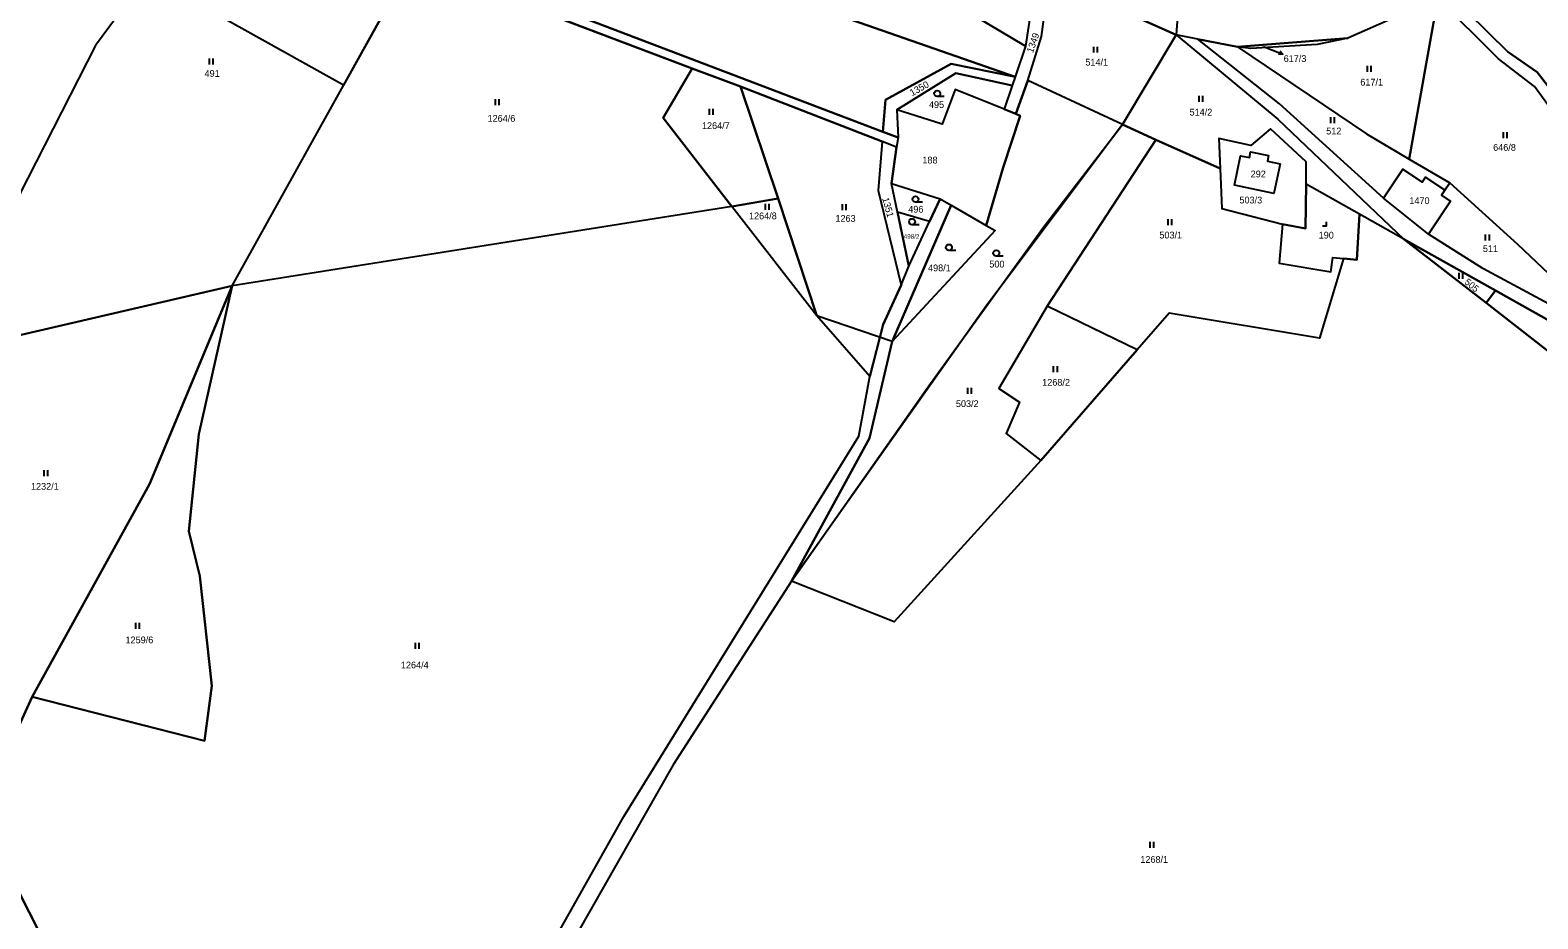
# Model space of a CAD drawing. Extents: x -588699 to -585793, y -1060280 to -1056731.
# Drawn here: x -586660.9 to -586283.2, y -1059020.2 to -1058797.6 of the extents above; entities that cross this region are included whole.
import ezdxf

# ---------------------------------------------------------------- set-up
doc = ezdxf.new("R2010")
doc.units = 0
for name, color, linetype in [('Druh pozemku', 7, 'Continuous'), ('Lesy', 7, 'Continuous'), ('Neřešené', 7, 'Continuous'), ('Parcela nároku', 7, 'Continuous'), ('Parcelní číslo', 7, 'Continuous')]:
    doc.layers.add(name, color=color, linetype=linetype)

msp = doc.modelspace()

# ---------------------------------------------------------------- linework, layer by layer
at = {"layer": 'Druh pozemku'}
for p, q in [((-586394.56, -1058801.77), (-586394.56, -1058803.27)), ((-586393.54, -1058803.27), (-586393.54, -1058801.77)), ((-586616.06, -1058804.73), (-586616.06, -1058806.23)), ((-586615.04, -1058806.23), (-586615.04, -1058804.73)), ((-586326.03, -1058806.53), (-586326.03, -1058808.03)), ((-586325.01, -1058808.03), (-586325.01, -1058806.53)), ((-586431.93, -1058814.25), (-586433.68, -1058814.25)), ((-586368.2, -1058814.07), (-586368.2, -1058815.57)), ((-586367.18, -1058815.57), (-586367.18, -1058814.07)), ((-586544.44, -1058814.9), (-586544.44, -1058816.4)), ((-586543.42, -1058816.4), (-586543.42, -1058814.9)), ((-586490.84, -1058817.34), (-586490.84, -1058818.84)), ((-586489.82, -1058818.84), (-586489.82, -1058817.34)), ((-586335.21, -1058819.43), (-586335.21, -1058820.93)), ((-586334.19, -1058820.93), (-586334.19, -1058819.43)), ((-586291.91, -1058823.19), (-586291.91, -1058824.69)), ((-586290.89, -1058824.69), (-586290.89, -1058823.19)), ((-586476.8, -1058841.1), (-586476.8, -1058842.6)), ((-586475.78, -1058842.6), (-586475.78, -1058841.1)), ((-586457.55, -1058841.23), (-586457.55, -1058842.73)), ((-586456.53, -1058842.73), (-586456.53, -1058841.23)), ((-586437.38, -1058840.71), (-586439.13, -1058840.71)), ((-586438.24, -1058846.36), (-586439.99, -1058846.36)), ((-586375.95, -1058844.99), (-586375.95, -1058846.49)), ((-586374.93, -1058846.49), (-586374.93, -1058844.99)), ((-586296.41, -1058848.82), (-586296.41, -1058850.32)), ((-586295.39, -1058850.32), (-586295.39, -1058848.82)), ((-586429.01, -1058852.78), (-586430.76, -1058852.78)), ((-586417.16, -1058854.22), (-586418.91, -1058854.22)), ((-586303.06, -1058858.37), (-586303.06, -1058859.87)), ((-586302.04, -1058859.87), (-586302.04, -1058858.37)), ((-586404.62, -1058881.79), (-586404.62, -1058883.29)), ((-586403.59, -1058883.29), (-586403.59, -1058881.79)), ((-586426.15, -1058887.17), (-586426.15, -1058888.67)), ((-586425.12, -1058888.67), (-586425.12, -1058887.17)), ((-586657.53, -1058907.8), (-586657.53, -1058909.3)), ((-586656.51, -1058909.3), (-586656.51, -1058907.8)), ((-586634.53, -1058946.07), (-586634.53, -1058947.57)), ((-586633.51, -1058947.57), (-586633.51, -1058946.07)), ((-586564.47, -1058951.05), (-586564.47, -1058952.55)), ((-586563.45, -1058952.55), (-586563.45, -1058951.05)), ((-586380.45, -1059000.86), (-586380.45, -1059002.36)), ((-586379.43, -1059002.36), (-586379.43, -1059000.86))]:
    msp.add_line(p, q, dxfattribs=at)
msp.add_lwpolyline([(-586337.18, -1058846.63), (-586336.18, -1058846.63), (-586336.18, -1058845.63)], dxfattribs=at)
for centre in [(-586433.68, -1058813.5), (-586439.13, -1058839.96), (-586439.99, -1058845.61), (-586430.76, -1058852.03), (-586418.91, -1058853.47)]:
    msp.add_circle(centre, 0.75, dxfattribs=at)
at = {"layer": 'Lesy'}
for p, q in [((-586582.39, -1058811.42), (-586631.56, -1058783.96)), ((-586565.27, -1058780.61), (-586582.39, -1058811.42)), ((-586495.05, -1058807.2), (-586565.27, -1058780.61)), ((-586373.25, -1058790.93), (-586373.84, -1058798.77)), ((-586373.84, -1058798.77), (-586387.33, -1058821.26)), ((-586502.31, -1058819.61), (-586495.05, -1058807.2)), ((-586485.18, -1058841.82), (-586502.31, -1058819.61)), ((-586387.33, -1058821.26), (-586421.24, -1058866.54)), ((-586463.88, -1058869.16), (-586485.18, -1058841.82)), ((-586421.24, -1058866.54), (-586470.2, -1058935.58)), ((-586445, -1058875.57), (-586463.88, -1058869.16)), ((-586450.63, -1058899.84), (-586445, -1058875.57)), ((-586470.2, -1058935.58), (-586450.63, -1058899.84))]:
    msp.add_line(p, q, dxfattribs=at)
at = {"layer": 'Neřešené'}
msp.add_lwpolyline([(-586359.27, -1058836.46), (-586357.69, -1058829.07), (-586355.49, -1058829.49), (-586355.22, -1058828.07), (-586350.68, -1058829.06), (-586350.99, -1058830.46), (-586347.82, -1058831.15), (-586349.42, -1058838.57)], close=True, dxfattribs=at)
at = {"layer": 'Parcela nároku'}
for points in [[(-586668.27, -1058711.07), (-586643.18, -1058723.44), (-586626.83, -1058736.19), (-586608.24, -1058752.75), (-586606, -1058754.58), (-586602.48, -1058757.45), (-586587.17, -1058767.71), (-586564.07, -1058778.59), (-586447.32, -1058823.07), (-586443.51, -1058824.52), (-586443.86, -1058826.94), (-586447.51, -1058825.52), (-586483.01, -1058811.75), (-586495.05, -1058807.2), (-586565.27, -1058780.61), (-586592.71, -1058770.73), (-586608.51, -1058756.38), (-586610.69, -1058754.4), (-586611.98, -1058753.23), (-586618.28, -1058747.51), (-586621.92, -1058744.2), (-586644.38, -1058725.27), (-586669.98, -1058713.39)], [(-586669.98, -1058713.39), (-586644.38, -1058725.27), (-586621.92, -1058744.2), (-586634.46, -1058760.51), (-586623.71, -1058768.4), (-586631.19, -1058778.4), (-586628.98, -1058780.48), (-586644.52, -1058801.5), (-586674.36, -1058859.75)], [(-586308.29, -1058789.63), (-586330.85, -1058799.68), (-586358.44, -1058801.82), (-586368.38, -1058799.85), (-586373.84, -1058798.77), (-586399.97, -1058787.16)], [(-586552.82, -1059066.58), (-586512.22, -1058994.58), (-586453.37, -1058899.27), (-586450.55, -1058884.37), (-586447.22, -1058871.37), (-586442.74, -1058861.51), (-586440.8, -1058856.75), (-586435.6, -1058845.55), (-586432.97, -1058839.9), (-586430.24, -1058841.49), (-586445, -1058875.57), (-586450.63, -1058899.84), (-586470.2, -1058935.58), (-586499.84, -1058981.58), (-586537.86, -1059048.29)], [(-586552.82, -1059066.58), (-586512.22, -1058994.58), (-586453.37, -1058899.27), (-586450.55, -1058884.37), (-586463.88, -1058869.16), (-586485.18, -1058841.82), (-586610.33, -1058861.7), (-586618.67, -1058898.83), (-586621.14, -1058923.14), (-586618.45, -1058934.36), (-586615.43, -1058961.85), (-586617.22, -1058975.6), (-586660.4, -1058964.58), (-586670.41, -1058986.49), (-586668.41, -1059004.17), (-586657.46, -1059025.77)], [(-586269.34, -1059045.64), (-586242.85, -1059015.4), (-586188.74, -1058958.67), (-586231.16, -1058919.67), (-586254.78, -1058898.23), (-586296.2, -1058865.92), (-586316.8, -1058849.98), (-586327.91, -1058843.73), (-586328.55, -1058855.16), (-586331.92, -1058854.82), (-586337.98, -1058874.74), (-586375.57, -1058868.5), (-586383.6, -1058877.69), (-586407.78, -1058905.38), (-586444.49, -1058945.77), (-586470.2, -1058935.58), (-586499.84, -1058981.58), (-586537.86, -1059048.29)]]:
    msp.add_lwpolyline(points, dxfattribs=at)
for points in [[(-586305.84, -1058788.1), (-586281.39, -1058771.68), (-586256.73, -1058759.17), (-586215.7, -1058740.44), (-586185.96, -1058731.13), (-586193.49, -1058744.57), (-586219.2, -1058783.33), (-586231.36, -1058799.16), (-586261.7, -1058840.18), (-586266.42, -1058830.14), (-586283.38, -1058808.16), (-586290.74, -1058803.04)], [(-586494.27, -1058770.47), (-586491.99, -1058772.91), (-586481.47, -1058783.92), (-586476.12, -1058778.86), (-586480.09, -1058774.77), (-586478.86, -1058773.56), (-586481.88, -1058770.42), (-586483.12, -1058771.65), (-586486.65, -1058768.06), (-586473.21, -1058764.89), (-586411.55, -1058801.66), (-586414.16, -1058809.35), (-586490.14, -1058782.82), (-586546.76, -1058750.88), (-586536, -1058737.73), (-586500.07, -1058758.34), (-586503, -1058761.17)], [(-586546.76, -1058750.88), (-586490.14, -1058782.82), (-586414.16, -1058809.35), (-586430.2, -1058806.03), (-586446.69, -1058815.09), (-586447.32, -1058823.07), (-586564.07, -1058778.59), (-586558, -1058770.65)], [(-586448.02, -1058760.9), (-586431.3, -1058770.3), (-586430.27, -1058767.88), (-586425.65, -1058772.84), (-586411.04, -1058780.99), (-586410.09, -1058791.78), (-586411.55, -1058801.66), (-586473.21, -1058764.89), (-586458.53, -1058750.26), (-586462.12, -1058759.77), (-586449.39, -1058764.8)], [(-586628.98, -1058780.48), (-586644.52, -1058801.5), (-586674.36, -1058859.75), (-586676.24, -1058869.35), (-586676.18, -1058876.91), (-586610.33, -1058861.7), (-586565.27, -1058780.61), (-586592.71, -1058770.73), (-586604.81, -1058784.17), (-586607.85, -1058781.62), (-586619.73, -1058773.04), (-586622.18, -1058771.27)], [(-586502.31, -1058819.61), (-586485.18, -1058841.82), (-586610.33, -1058861.7), (-586565.27, -1058780.61), (-586495.05, -1058807.2)], [(-586414.92, -1058811.53), (-586416.96, -1058817.42), (-586414.02, -1058818.61), (-586411.03, -1058810.24), (-586407.58, -1058799.23), (-586406.6, -1058791.8), (-586407.1, -1058783.18), (-586411.04, -1058780.99), (-586410.09, -1058791.78), (-586411.55, -1058801.66), (-586414.16, -1058809.35)], [(-586411.03, -1058810.24), (-586407.58, -1058799.23), (-586406.6, -1058791.8), (-586403.04, -1058785.45), (-586399.97, -1058787.16), (-586373.84, -1058798.77), (-586387.33, -1058821.26)], [(-586308.29, -1058789.63), (-586330.85, -1058799.68), (-586338.52, -1058801.23), (-586355.15, -1058802.25), (-586358.44, -1058801.82), (-586326.2, -1058823.63), (-586315.44, -1058829.9)], [(-586270.72, -1058830.12), (-586284.05, -1058811.77), (-586293.09, -1058804.81), (-586308.29, -1058789.63), (-586315.44, -1058829.9), (-586305.28, -1058835.83), (-586288.31, -1058851.23), (-586277.39, -1058861.56), (-586265.16, -1058839.87)], [(-586308.29, -1058789.63), (-586305.84, -1058788.1), (-586290.74, -1058803.04), (-586283.38, -1058808.16), (-586266.42, -1058830.14), (-586261.7, -1058840.18), (-586232.96, -1058858.44), (-586210.37, -1058875.49), (-586200.6, -1058882.87), (-586192.2, -1058897.74), (-586179.85, -1058912.85), (-586154.34, -1058936.8), (-586157.46, -1058938.24), (-586175.66, -1058921.09), (-586195.55, -1058899.89), (-586202.53, -1058884.11), (-586233.05, -1058861.42), (-586263.54, -1058842.71), (-586265.16, -1058839.87), (-586270.72, -1058830.12), (-586284.05, -1058811.77), (-586293.09, -1058804.81)], [(-586348.39, -1058819.94), (-586316.8, -1058849.98), (-586327.91, -1058843.73), (-586341.28, -1058836.21), (-586341.28, -1058830.57), (-586350.24, -1058822.35), (-586355.15, -1058826.53), (-586363.17, -1058824.74), (-586362.83, -1058832.3), (-586378.98, -1058825.14), (-586387.33, -1058821.26), (-586373.84, -1058798.77)], [(-586280.54, -1058866.15), (-586297.04, -1058857.32), (-586310.6, -1058848.71), (-586321.9, -1058839.68), (-586348, -1058816.05), (-586368.38, -1058799.85), (-586373.84, -1058798.77), (-586348.39, -1058819.94), (-586316.8, -1058849.98), (-586293.88, -1058862.81), (-586275.7, -1058872.99), (-586253.24, -1058893.35), (-586228.24, -1058916.68), (-586199.1, -1058944.35), (-586189.67, -1058949.82), (-586177, -1058948.8), (-586175.32, -1058947.51), (-586187.84, -1058948.03), (-586197.46, -1058942.53), (-586217.06, -1058922.93), (-586249.55, -1058890.62), (-586273.66, -1058870), (-586278.25, -1058867.56)], [(-586315.44, -1058829.9), (-586305.28, -1058835.83), (-586306.57, -1058837.73), (-586311.38, -1058834.49), (-586312.2, -1058835.72), (-586317.06, -1058832.47), (-586321.9, -1058839.68), (-586348, -1058816.05), (-586368.38, -1058799.85), (-586358.44, -1058801.82), (-586326.2, -1058823.63)], [(-586358.44, -1058801.82), (-586330.85, -1058799.68), (-586338.52, -1058801.23), (-586355.15, -1058802.25)], [(-586443.79, -1058817.55), (-586443.51, -1058824.52), (-586447.32, -1058823.07), (-586446.69, -1058815.09), (-586430.2, -1058806.03), (-586414.16, -1058809.35), (-586414.92, -1058811.53), (-586429.06, -1058808.42)], [(-586483.01, -1058811.75), (-586473.57, -1058839.82), (-586485.18, -1058841.82), (-586502.31, -1058819.61), (-586495.05, -1058807.2)], [(-586411.03, -1058810.24), (-586414.02, -1058818.61), (-586412.92, -1058819.05), (-586417.14, -1058832.07), (-586421.48, -1058846.57), (-586419.17, -1058847.8), (-586445, -1058875.57), (-586450.63, -1058899.84), (-586470.2, -1058935.58), (-586435.42, -1058886.13), (-586407.05, -1058846.94), (-586387.33, -1058821.26)], [(-586443.79, -1058817.55), (-586429.06, -1058808.42), (-586414.92, -1058811.53), (-586416.96, -1058817.42), (-586429.19, -1058812.49), (-586432.43, -1058821.2), (-586439.06, -1058819.07)], [(-586448.48, -1058837.76), (-586442.74, -1058861.51), (-586447.22, -1058871.37), (-586450.55, -1058884.37), (-586463.88, -1058869.16), (-586473.57, -1058839.82), (-586483.01, -1058811.75), (-586447.51, -1058825.52)], [(-586432.43, -1058821.2), (-586439.06, -1058819.07), (-586443.79, -1058817.55), (-586443.51, -1058824.52), (-586443.86, -1058826.94), (-586445.14, -1058836.05), (-586432.97, -1058839.9), (-586430.24, -1058841.49), (-586421.48, -1058846.57), (-586417.14, -1058832.07), (-586412.92, -1058819.05), (-586414.02, -1058818.61), (-586416.96, -1058817.42), (-586429.19, -1058812.49)], [(-586435.42, -1058886.13), (-586407.05, -1058846.94), (-586387.33, -1058821.26), (-586378.98, -1058825.14), (-586406.15, -1058866.73), (-586418.25, -1058887.39), (-586413.13, -1058890.82), (-586416.46, -1058898.64), (-586407.78, -1058905.38), (-586444.49, -1058945.77), (-586470.2, -1058935.58)], [(-586443.86, -1058826.94), (-586447.51, -1058825.52), (-586448.48, -1058837.76), (-586442.74, -1058861.51), (-586440.8, -1058856.75), (-586443.64, -1058843.21), (-586445.14, -1058836.05)], [(-586378.98, -1058825.14), (-586362.83, -1058832.3), (-586362.38, -1058842.32), (-586347.23, -1058846.18), (-586348.07, -1058856), (-586335.09, -1058858.17), (-586334.62, -1058854.55), (-586331.92, -1058854.82), (-586337.98, -1058874.74), (-586375.57, -1058868.5), (-586383.6, -1058877.69), (-586406.15, -1058866.73)], [(-586341.28, -1058830.57), (-586350.24, -1058822.35), (-586355.15, -1058826.53), (-586363.17, -1058824.74), (-586362.83, -1058832.3), (-586362.38, -1058842.32), (-586347.23, -1058846.18), (-586341.45, -1058847.32), (-586341.28, -1058836.21)], [(-586350.68, -1058829.06), (-586350.99, -1058830.46), (-586347.82, -1058831.15), (-586349.42, -1058838.57), (-586359.27, -1058836.46), (-586357.69, -1058829.07), (-586355.49, -1058829.49), (-586355.22, -1058828.07)], [(-586355.49, -1058829.49), (-586355.22, -1058828.07), (-586350.68, -1058829.06), (-586350.99, -1058830.46), (-586347.82, -1058831.15), (-586349.42, -1058838.57), (-586359.27, -1058836.46), (-586357.69, -1058829.07)], [(-586307.39, -1058838.94), (-586305.11, -1058840.47), (-586310.6, -1058848.71), (-586321.9, -1058839.68), (-586317.06, -1058832.47), (-586312.2, -1058835.72), (-586311.38, -1058834.49), (-586306.57, -1058837.73)], [(-586445.14, -1058836.05), (-586432.97, -1058839.9), (-586435.6, -1058845.55), (-586443.64, -1058843.21)], [(-586341.28, -1058836.21), (-586341.45, -1058847.32), (-586347.23, -1058846.18), (-586348.07, -1058856), (-586335.09, -1058858.17), (-586334.62, -1058854.55), (-586331.92, -1058854.82), (-586328.55, -1058855.16), (-586327.91, -1058843.73)], [(-586307.39, -1058838.94), (-586306.57, -1058837.73), (-586305.28, -1058835.83), (-586288.31, -1058851.23), (-586277.39, -1058861.56), (-586275.68, -1058863.17), (-586278.25, -1058867.56), (-586280.54, -1058866.15), (-586297.04, -1058857.32), (-586310.6, -1058848.71), (-586305.11, -1058840.47)], [(-586485.18, -1058841.82), (-586473.57, -1058839.82), (-586463.88, -1058869.16)], [(-586421.48, -1058846.57), (-586419.17, -1058847.8), (-586445, -1058875.57), (-586430.24, -1058841.49)], [(-586435.6, -1058845.55), (-586443.64, -1058843.21), (-586440.8, -1058856.75)], [(-586293.88, -1058862.81), (-586316.8, -1058849.98), (-586296.2, -1058865.92)], [(-586677.59, -1058961.14), (-586683.16, -1058975.11), (-586674.2, -1058992.76), (-586670.41, -1058986.49), (-586660.4, -1058964.58), (-586630.99, -1058911.29), (-586610.33, -1058861.7), (-586676.18, -1058876.91), (-586675.71, -1058936.99)], [(-586630.99, -1058911.29), (-586660.4, -1058964.58), (-586617.22, -1058975.6), (-586615.43, -1058961.85), (-586618.45, -1058934.36), (-586621.14, -1058923.14), (-586618.67, -1058898.83), (-586610.33, -1058861.7)], [(-586253.24, -1058893.35), (-586275.7, -1058872.99), (-586293.88, -1058862.81), (-586296.2, -1058865.92), (-586254.78, -1058898.23)], [(-586406.15, -1058866.73), (-586418.25, -1058887.39), (-586413.13, -1058890.82), (-586416.46, -1058898.64), (-586407.78, -1058905.38), (-586383.6, -1058877.69)], [(-586654.38, -1059073.26), (-586653.09, -1059041.46), (-586657.46, -1059025.77), (-586668.41, -1059004.17), (-586674.2, -1058992.76), (-586678.4, -1058999.7), (-586662.46, -1059031.85)]]:
    msp.add_lwpolyline(points, close=True, dxfattribs=at)
at = {"layer": 'Parcelní číslo'}
for p, q in [((-586352.01, -1058801.76), (-586349.89, -1058802.56)), ((-586349.89, -1058802.56), (-586347.09, -1058803.63))]:
    msp.add_line(p, q, dxfattribs=at)
msp.add_lwpolyline([(-586347.84, -1058802.81), (-586347.09, -1058803.63), (-586348.2, -1058803.74)], dxfattribs=at)

# ---------------------------------------------------------------- texts
at = {"layer": 'Parcela nároku'}
for s, rotation, p in [('1349', 70.912, (-586409.74, -1058803.47)), ('1350', 29.1554, (-586439.99, -1058814.21)), ('1351', 285.273, (-586447.5, -1058839.79)), ('505', 320.1114, (-586301.78, -1058860.97))]:
    msp.add_text(s, height=1.7, rotation=rotation, dxfattribs=at).set_placement(p)
for s, height, p in [('617/3', 0.1, (-586352.17, -1058801.76)), ('514/1', 1.7, (-586396.59, -1058806.51)), ('491', 1.7, (-586617.23, -1058809.33)), ('617/1', 1.7, (-586327.72, -1058811.51)), ('495', 1.7, (-586435.77, -1058817.13)), ('514/2', 1.7, (-586370.49, -1058819.03)), ('1264/6', 1.7, (-586546.34, -1058820.58)), ('1264/7', 1.7, (-586492.63, -1058822.4)), ('512', 1.7, (-586336.26, -1058823.75)), ('188', 1.7, (-586437.41, -1058831.02)), ('646/8', 1.7, (-586294.44, -1058827.84)), ('292', 1.7, (-586355.18, -1058834.5)), ('503/3', 1.7, (-586357.99, -1058841.03)), ('1470', 1.7, (-586315.43, -1058841.19)), ('1264/8', 1.7, (-586480.85, -1058845)), ('1263', 1.7, (-586459.2, -1058845.63)), ('496', 1.7, (-586440.95, -1058843.33)), ('503/1', 1.7, (-586378.05, -1058849.8)), ('190', 1.7, (-586338.15, -1058849.82)), ('498/2', 1.14, (-586442.09, -1058849.87)), ('511', 1.7, (-586297.02, -1058853.2)), ('500', 1.7, (-586420.65, -1058857.07)), ('498/1', 1.7, (-586436, -1058858.02)), ('1268/2', 1.7, (-586407.4, -1058886.68)), ('503/2', 1.7, (-586429.02, -1058892.02)), ('1232/1', 1.7, (-586660.71, -1058912.72)), ('1259/6', 1.7, (-586637.03, -1058951.18)), ('1264/4', 1.7, (-586568.05, -1058957.47)), ('1268/1', 1.7, (-586382.82, -1059006.16))]:
    msp.add_text(s, height=height, dxfattribs=at).set_placement(p)
at = {"layer": 'Parcelní číslo'}
msp.add_text('617/3', height=1.7, dxfattribs=at).set_placement((-586346.92, -1058805.6))

doc.saveas('drawing.dxf')
